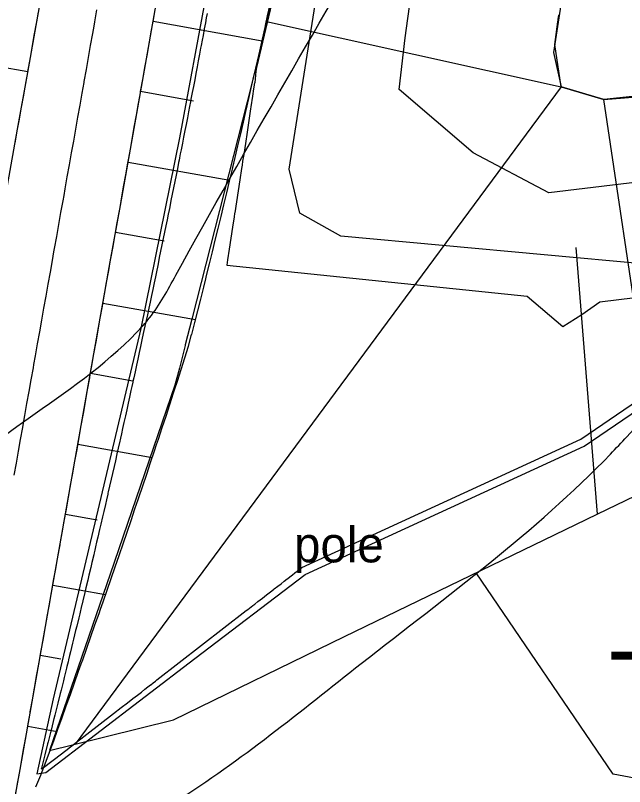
# Model space of a CAD drawing. Extents: x -564043 to -563833, y -1163561 to -1163412.
# Drawn here: x -563931 to -563920.35, y -1163501.37 to -1163487.91 of the extents above; entities that cross this region are included whole.
import ezdxf

# ---------------------------------------------------------------- set-up
doc = ezdxf.new("R2010")
doc.units = 0
for name, color, linetype in [('4', 7, 'Continuous'), ('Default', 7, 'Continuous'), ('Line', 7, 'Continuous'), ('Vrstva 24', 7, 'Continuous'), ('Vrstva 26', 7, 'Continuous'), ('Vrstva 40', 7, 'Continuous')]:
    doc.layers.add(name, color=color, linetype=linetype)

msp = doc.modelspace()

# ---------------------------------------------------------------- linework, layer by layer
msp.add_line((-563930.546, -1163501.066), (-563930.51, -1163501.042))
for points in [[(-563930.469, -1163501.126), (-563927.863, -1163499.14), (-563925.937, -1163497.674), (-563921.059, -1163495.43), (-563912.613, -1163489.681), (-563911.421, -1163482.517), (-563913.266, -1163479.715), (-563914.137, -1163478.749), (-563916.309, -1163476.467), (-563917.281, -1163475.995), (-563923.761, -1163471.506), (-563924, -1163472.797), (-563925.435, -1163477.844), (-563927.008, -1163483.992), (-563927.659, -1163487.507), (-563928.13, -1163490.05), (-563928.806, -1163493.379), (-563930.34, -1163499.841), (-563930.622, -1163501.15)], [(-563915.586, -1163481.384), (-563914.537, -1163483.686), (-563915.595, -1163487.753), (-563917.092, -1163490.681), (-563919.984, -1163492.255), (-563925.31, -1163491.764), (-563926.027, -1163491.364), (-563926.218, -1163490.597), (-563925.375, -1163485.285), (-563924.678, -1163482.734), (-563924.029, -1163478.524), (-563922.899, -1163477.259), (-563919.326, -1163477.602), (-563916.674, -1163478.991)]]:
    msp.add_lwpolyline(points, close=True)
for points in [[(-563925.566, -1163483.68), (-563926.788, -1163488.822), (-563926.795, -1163488.885), (-563926.811, -1163489.025), (-563926.818, -1163489.08), (-563926.823, -1163489.098), (-563926.825, -1163489.11), (-563926.827, -1163489.131), (-563926.837, -1163489.194), (-563926.856, -1163489.32), (-563926.883, -1163489.509), (-563926.89, -1163489.542), (-563926.896, -1163489.586), (-563926.921, -1163489.749), (-563926.952, -1163489.951), (-563926.981, -1163490.148), (-563927.01, -1163490.339), (-563927.028, -1163490.459), (-563927.038, -1163490.526), (-563927.048, -1163490.584), (-563927.078, -1163490.781), (-563927.108, -1163490.976), (-563927.137, -1163491.167), (-563927.166, -1163491.356), (-563927.168, -1163491.368), (-563927.177, -1163491.426), (-563927.205, -1163491.609), (-563927.235, -1163491.802), (-563927.264, -1163491.992), (-563927.292, -1163492.181), (-563927.306, -1163492.273), (-563922.057, -1163492.813), (-563921.435, -1163493.345), (-563921.102, -1163493.131), (-563920.787, -1163492.909), (-563919.265, -1163492.727)], [(-563921.157, -1163485.676), (-563921.598, -1163488.562), (-563921.461, -1163489.159), (-563920.716, -1163489.381), (-563919.058, -1163489.245), (-563919.058, -1163489.245), (-563919.058, -1163489.245), (-563916.75, -1163488.907), (-563916.212, -1163488.994), (-563914.24, -1163489.313), (-563912.713, -1163485.924)], [(-563919.165, -1163490.707), (-563921.676, -1163491.008), (-563923.002, -1163490.31), (-563924.293, -1163489.206), (-563924.187, -1163488.301), (-563923.991, -1163486.868)], [(-563933.061, -1163501.709), (-563932.976, -1163501.232), (-563932.886, -1163500.725), (-563932.71, -1163499.74), (-563932.535, -1163498.756), (-563932.36, -1163497.771), (-563932.185, -1163496.786), (-563932.01, -1163495.802), (-563931.835, -1163494.817), (-563931.659, -1163493.833), (-563931.484, -1163492.848), (-563931.404, -1163492.395), (-563931.309, -1163491.864), (-563931.134, -1163490.879), (-563930.959, -1163489.895), (-563930.784, -1163488.91), (-563930.608, -1163487.926), (-563930.509, -1163487.367)], [(-563931.018, -1163495.937), (-563930.981, -1163495.729), (-563930.944, -1163495.521), (-563930.907, -1163495.313), (-563930.87, -1163495.104), (-563930.85, -1163494.993), (-563930.833, -1163494.896), (-563930.796, -1163494.688), (-563930.759, -1163494.479), (-563930.722, -1163494.271), (-563930.685, -1163494.063), (-563930.675, -1163494.008), (-563930.648, -1163493.854), (-563930.611, -1163493.646), (-563930.573, -1163493.438), (-563930.536, -1163493.23), (-563930.5, -1163493.024), (-563930.499, -1163493.021), (-563930.462, -1163492.813), (-563930.425, -1163492.605), (-563930.388, -1163492.396), (-563930.351, -1163492.188), (-563930.325, -1163492.039), (-563930.314, -1163491.98), (-563930.277, -1163491.771), (-563930.24, -1163491.563), (-563930.203, -1163491.355), (-563930.166, -1163491.147), (-563930.149, -1163491.054), (-563930.129, -1163490.938), (-563930.092, -1163490.73), (-563930.055, -1163490.522), (-563930.018, -1163490.313), (-563929.98, -1163490.105), (-563929.974, -1163490.07), (-563929.943, -1163489.897), (-563929.906, -1163489.688), (-563929.869, -1163489.48), (-563929.832, -1163489.272), (-563929.799, -1163489.085), (-563929.795, -1163489.064), (-563929.758, -1163488.855), (-563929.721, -1163488.647), (-563929.684, -1163488.439), (-563929.647, -1163488.23), (-563929.624, -1163488.101), (-563929.61, -1163488.022), (-563929.573, -1163487.814)], [(-563931.007, -1163501.582), (-563930.917, -1163501.075), (-563930.741, -1163500.09), (-563930.566, -1163499.106), (-563930.391, -1163498.121), (-563930.216, -1163497.137), (-563930.041, -1163496.152), (-563929.866, -1163495.168), (-563929.69, -1163494.183), (-563929.515, -1163493.199), (-563929.435, -1163492.745), (-563929.34, -1163492.214), (-563929.165, -1163491.23), (-563928.99, -1163490.245), (-563928.815, -1163489.261), (-563928.639, -1163488.276), (-563928.54, -1163487.717)], [(-563931.002, -1163490.138), (-563930.965, -1163489.93), (-563930.959, -1163489.895), (-563930.928, -1163489.722), (-563930.891, -1163489.513), (-563930.854, -1163489.305), (-563930.817, -1163489.097), (-563930.784, -1163488.91), (-563930.78, -1163488.888), (-563930.743, -1163488.68), (-563930.706, -1163488.472), (-563930.669, -1163488.264), (-563930.631, -1163488.055), (-563930.608, -1163487.926), (-563930.594, -1163487.847)], [(-563931.002, -1163490.138), (-563930.965, -1163489.93), (-563930.959, -1163489.895), (-563930.928, -1163489.722), (-563930.891, -1163489.513), (-563930.854, -1163489.305), (-563930.817, -1163489.097), (-563930.784, -1163488.91), (-563930.78, -1163488.888), (-563930.743, -1163488.68), (-563930.706, -1163488.472), (-563930.669, -1163488.264), (-563930.631, -1163488.055), (-563930.608, -1163487.926), (-563930.594, -1163487.847)], [(-563930.997, -1163501.528), (-563930.96, -1163501.32), (-563930.923, -1163501.112), (-563930.917, -1163501.075), (-563930.886, -1163500.904), (-563930.849, -1163500.695), (-563930.812, -1163500.487), (-563930.775, -1163500.279), (-563930.741, -1163500.09), (-563930.738, -1163500.07), (-563930.701, -1163499.862), (-563930.664, -1163499.654), (-563930.627, -1163499.445), (-563930.59, -1163499.237), (-563930.566, -1163499.106), (-563930.553, -1163499.029), (-563930.515, -1163498.821), (-563930.478, -1163498.612), (-563930.441, -1163498.404), (-563930.404, -1163498.196), (-563930.391, -1163498.121), (-563930.367, -1163497.987), (-563930.33, -1163497.779), (-563930.293, -1163497.571), (-563930.256, -1163497.362), (-563930.219, -1163497.154), (-563930.216, -1163497.137), (-563930.182, -1163496.946), (-563930.145, -1163496.738), (-563930.108, -1163496.529), (-563930.071, -1163496.321), (-563930.041, -1163496.152), (-563930.034, -1163496.113), (-563929.997, -1163495.904), (-563929.96, -1163495.696), (-563929.922, -1163495.488), (-563929.885, -1163495.279), (-563929.866, -1163495.168), (-563929.848, -1163495.071), (-563929.811, -1163494.863), (-563929.774, -1163494.655), (-563929.737, -1163494.446), (-563929.7, -1163494.238), (-563929.69, -1163494.183), (-563929.663, -1163494.03), (-563929.626, -1163493.821), (-563929.589, -1163493.613), (-563929.552, -1163493.405), (-563929.515, -1163493.199), (-563929.515, -1163493.196), (-563929.478, -1163492.988), (-563929.441, -1163492.78), (-563929.404, -1163492.572), (-563929.367, -1163492.363), (-563929.34, -1163492.214), (-563929.33, -1163492.155), (-563929.292, -1163491.947), (-563929.255, -1163491.738), (-563929.218, -1163491.53), (-563929.181, -1163491.322), (-563929.165, -1163491.23), (-563929.144, -1163491.113), (-563929.107, -1163490.905), (-563929.07, -1163490.697), (-563929.033, -1163490.489), (-563928.996, -1163490.28), (-563928.99, -1163490.245), (-563928.959, -1163490.072), (-563928.922, -1163489.864), (-563928.885, -1163489.655), (-563928.848, -1163489.447), (-563928.815, -1163489.261), (-563928.811, -1163489.239), (-563928.774, -1163489.03), (-563928.737, -1163488.822), (-563928.699, -1163488.614), (-563928.662, -1163488.406), (-563928.639, -1163488.276), (-563928.625, -1163488.197), (-563928.588, -1163487.989), (-563928.551, -1163487.781)], [(-563930.997, -1163501.528), (-563930.96, -1163501.32), (-563930.923, -1163501.112), (-563930.917, -1163501.075), (-563930.886, -1163500.904), (-563930.849, -1163500.695), (-563930.812, -1163500.487), (-563930.775, -1163500.279), (-563930.741, -1163500.09), (-563930.738, -1163500.07), (-563930.701, -1163499.862), (-563930.664, -1163499.654), (-563930.627, -1163499.445), (-563930.59, -1163499.237), (-563930.566, -1163499.106), (-563930.553, -1163499.029), (-563930.515, -1163498.821), (-563930.478, -1163498.612), (-563930.441, -1163498.404), (-563930.404, -1163498.196), (-563930.391, -1163498.121), (-563930.367, -1163497.987), (-563930.33, -1163497.779), (-563930.293, -1163497.571), (-563930.256, -1163497.362), (-563930.219, -1163497.154), (-563930.216, -1163497.137), (-563930.182, -1163496.946), (-563930.145, -1163496.738), (-563930.108, -1163496.529), (-563930.071, -1163496.321), (-563930.041, -1163496.152), (-563930.034, -1163496.113), (-563929.997, -1163495.904), (-563929.96, -1163495.696), (-563929.922, -1163495.488), (-563929.885, -1163495.279), (-563929.866, -1163495.168), (-563929.848, -1163495.071), (-563929.811, -1163494.863), (-563929.774, -1163494.655), (-563929.737, -1163494.446), (-563929.7, -1163494.238), (-563929.69, -1163494.183), (-563929.663, -1163494.03), (-563929.626, -1163493.821), (-563929.589, -1163493.613), (-563929.552, -1163493.405), (-563929.515, -1163493.199), (-563929.515, -1163493.196), (-563929.478, -1163492.988), (-563929.441, -1163492.78), (-563929.404, -1163492.572), (-563929.367, -1163492.363), (-563929.34, -1163492.214), (-563929.33, -1163492.155), (-563929.292, -1163491.947), (-563929.255, -1163491.738), (-563929.218, -1163491.53), (-563929.181, -1163491.322), (-563929.165, -1163491.23), (-563929.144, -1163491.113), (-563929.107, -1163490.905), (-563929.07, -1163490.697), (-563929.033, -1163490.489), (-563928.996, -1163490.28), (-563928.99, -1163490.245), (-563928.959, -1163490.072), (-563928.922, -1163489.864), (-563928.885, -1163489.655), (-563928.848, -1163489.447), (-563928.815, -1163489.261), (-563928.811, -1163489.239), (-563928.774, -1163489.03), (-563928.737, -1163488.822), (-563928.699, -1163488.614), (-563928.662, -1163488.406), (-563928.639, -1163488.276), (-563928.625, -1163488.197), (-563928.588, -1163487.989), (-563928.551, -1163487.781)], [(-563930.64, -1163501.377), (-563930.555, -1163501.177), (-563930.54, -1163501.142), (-563930.476, -1163500.976), (-563930.403, -1163500.775), (-563930.329, -1163500.573), (-563930.256, -1163500.371), (-563930.19, -1163500.188), (-563930.183, -1163500.169), (-563930.111, -1163499.967), (-563930.038, -1163499.765), (-563929.966, -1163499.563), (-563929.894, -1163499.361), (-563929.849, -1163499.234), (-563929.822, -1163499.159), (-563929.751, -1163498.957), (-563929.679, -1163498.754), (-563929.608, -1163498.552), (-563929.537, -1163498.35), (-563929.512, -1163498.278), (-563929.467, -1163498.148), (-563929.396, -1163497.945), (-563929.326, -1163497.743), (-563929.256, -1163497.54), (-563929.186, -1163497.338), (-563929.181, -1163497.321), (-563929.117, -1163497.135), (-563929.048, -1163496.933), (-563928.978, -1163496.73), (-563928.91, -1163496.528), (-563928.854, -1163496.363), (-563928.841, -1163496.325), (-563928.773, -1163496.122), (-563928.704, -1163495.919), (-563928.637, -1163495.717), (-563928.569, -1163495.514), (-563928.533, -1163495.405), (-563928.501, -1163495.311), (-563928.434, -1163495.108), (-563928.367, -1163494.905), (-563928.3, -1163494.702), (-563928.234, -1163494.499), (-563928.216, -1163494.446), (-563928.167, -1163494.296), (-563928.101, -1163494.093), (-563928.036, -1163493.889), (-563927.972, -1163493.686), (-563927.919, -1163493.483), (-563927.918, -1163493.481), (-563927.864, -1163493.275), (-563927.812, -1163493.07), (-563927.76, -1163492.864), (-563927.709, -1163492.658), (-563927.672, -1163492.511), (-563927.658, -1163492.452), (-563927.607, -1163492.247), (-563927.556, -1163492.041), (-563927.506, -1163491.835), (-563927.456, -1163491.629), (-563927.434, -1163491.538), (-563927.406, -1163491.423), (-563927.356, -1163491.217), (-563927.306, -1163491.011), (-563927.257, -1163490.805), (-563927.208, -1163490.598), (-563927.2, -1163490.564), (-563927.159, -1163490.392), (-563927.111, -1163490.186), (-563927.062, -1163489.98), (-563927.014, -1163489.773), (-563926.971, -1163489.589), (-563926.966, -1163489.567), (-563926.918, -1163489.361), (-563926.871, -1163489.154), (-563926.824, -1163488.948), (-563926.776, -1163488.741), (-563926.747, -1163488.613), (-563926.73, -1163488.535), (-563926.683, -1163488.328), (-563926.637, -1163488.121), (-563926.622, -1163488.058), (-563926.592, -1163487.92), (-563926.547, -1163487.722)], [(-563930.64, -1163501.377), (-563930.555, -1163501.177), (-563930.54, -1163501.142), (-563930.476, -1163500.976), (-563930.403, -1163500.775), (-563930.329, -1163500.573), (-563930.256, -1163500.371), (-563930.19, -1163500.188), (-563930.183, -1163500.169), (-563930.111, -1163499.967), (-563930.038, -1163499.765), (-563929.966, -1163499.563), (-563929.894, -1163499.361), (-563929.849, -1163499.234), (-563929.822, -1163499.159), (-563929.751, -1163498.957), (-563929.679, -1163498.754), (-563929.608, -1163498.552), (-563929.537, -1163498.35), (-563929.512, -1163498.278), (-563929.467, -1163498.148), (-563929.396, -1163497.945), (-563929.326, -1163497.743), (-563929.256, -1163497.54), (-563929.186, -1163497.338), (-563929.181, -1163497.321), (-563929.117, -1163497.135), (-563929.048, -1163496.933), (-563928.978, -1163496.73), (-563928.91, -1163496.528), (-563928.854, -1163496.363), (-563928.841, -1163496.325), (-563928.773, -1163496.122), (-563928.704, -1163495.919), (-563928.637, -1163495.717), (-563928.569, -1163495.514), (-563928.533, -1163495.405), (-563928.501, -1163495.311), (-563928.434, -1163495.108), (-563928.367, -1163494.905), (-563928.3, -1163494.702), (-563928.234, -1163494.499), (-563928.216, -1163494.446), (-563928.167, -1163494.296), (-563928.101, -1163494.093), (-563928.036, -1163493.889), (-563927.972, -1163493.686), (-563927.919, -1163493.483), (-563927.918, -1163493.481), (-563927.864, -1163493.275), (-563927.812, -1163493.07), (-563927.76, -1163492.864), (-563927.709, -1163492.658), (-563927.672, -1163492.511), (-563927.658, -1163492.452), (-563927.607, -1163492.247), (-563927.556, -1163492.041), (-563927.506, -1163491.835), (-563927.456, -1163491.629), (-563927.434, -1163491.538), (-563927.406, -1163491.423), (-563927.356, -1163491.217), (-563927.306, -1163491.011), (-563927.257, -1163490.805), (-563927.208, -1163490.598), (-563927.2, -1163490.564), (-563927.159, -1163490.392), (-563927.111, -1163490.186), (-563927.062, -1163489.98), (-563927.014, -1163489.773), (-563926.971, -1163489.589), (-563926.966, -1163489.567), (-563926.918, -1163489.361), (-563926.871, -1163489.154), (-563926.824, -1163488.948), (-563926.776, -1163488.741), (-563926.747, -1163488.613), (-563926.73, -1163488.535), (-563926.683, -1163488.328), (-563926.637, -1163488.121), (-563926.622, -1163488.058), (-563926.592, -1163487.92), (-563926.547, -1163487.722)], [(-563927.649, -1163487.877), (-563927.663, -1163487.953), (-563927.679, -1163488.04), (-563927.698, -1163488.144), (-563927.72, -1163488.262), (-563927.736, -1163488.344), (-563927.753, -1163488.436), (-563927.757, -1163488.458), (-563927.762, -1163488.484), (-563927.782, -1163488.589), (-563927.804, -1163488.706), (-563927.824, -1163488.812), (-563927.846, -1163488.928), (-563927.866, -1163489.034), (-563927.888, -1163489.15), (-563927.909, -1163489.256), (-563927.931, -1163489.372), (-563927.935, -1163489.394), (-563927.94, -1163489.418), (-563927.956, -1163489.502), (-563927.974, -1163489.593), (-563927.994, -1163489.7), (-563928.017, -1163489.815), (-563928.038, -1163489.922), (-563928.06, -1163490.037), (-563928.081, -1163490.144), (-563928.104, -1163490.258), (-563928.117, -1163490.327), (-563928.131, -1163490.4), (-563928.139, -1163490.439), (-563928.147, -1163490.48), (-563928.169, -1163490.588), (-563928.192, -1163490.702), (-563928.213, -1163490.81), (-563928.236, -1163490.923), (-563928.258, -1163491.032), (-563928.28, -1163491.145), (-563928.302, -1163491.253), (-563928.325, -1163491.366), (-563928.327, -1163491.373), (-563928.328, -1163491.38), (-563928.349, -1163491.482), (-563928.37, -1163491.587), (-563928.393, -1163491.696), (-563928.416, -1163491.809), (-563928.438, -1163491.918), (-563928.461, -1163492.03), (-563928.484, -1163492.139), (-563928.507, -1163492.251), (-563928.518, -1163492.305), (-563928.53, -1163492.36), (-563928.541, -1163492.416), (-563928.553, -1163492.473), (-563928.576, -1163492.582), (-563928.6, -1163492.694), (-563928.623, -1163492.803), (-563928.646, -1163492.915), (-563928.669, -1163493.025), (-563928.693, -1163493.136), (-563928.715, -1163493.237), (-563928.736, -1163493.339), (-563928.738, -1163493.348), (-563928.74, -1163493.357), (-563928.764, -1163493.467), (-563928.787, -1163493.578), (-563928.811, -1163493.689), (-563928.835, -1163493.799), (-563928.859, -1163493.911), (-563928.883, -1163494.02), (-563928.908, -1163494.133), (-563928.931, -1163494.241), (-563928.94, -1163494.28), (-563928.948, -1163494.317), (-563928.964, -1163494.392), (-563928.979, -1163494.461), (-563929.005, -1163494.577), (-563929.028, -1163494.682), (-563929.054, -1163494.799), (-563929.077, -1163494.903), (-563929.103, -1163495.021), (-563929.126, -1163495.123), (-563929.147, -1163495.215), (-563929.164, -1163495.294), (-563929.17, -1163495.321), (-563929.175, -1163495.344), (-563929.202, -1163495.465), (-563929.225, -1163495.565), (-563929.252, -1163495.687), (-563929.275, -1163495.785), (-563929.303, -1163495.908), (-563929.325, -1163496.006), (-563929.353, -1163496.13), (-563929.375, -1163496.226), (-563929.381, -1163496.251), (-563929.385, -1163496.271), (-563929.409, -1163496.371), (-563929.426, -1163496.447), (-563929.455, -1163496.574), (-563929.477, -1163496.667), (-563929.507, -1163496.796), (-563929.528, -1163496.887), (-563929.558, -1163497.018), (-563929.579, -1163497.107), (-563929.599, -1163497.191), (-563929.612, -1163497.246), (-563929.623, -1163497.295), (-563929.631, -1163497.328), (-563929.663, -1163497.463), (-563929.683, -1163497.548), (-563929.715, -1163497.685), (-563929.735, -1163497.768), (-563929.768, -1163497.907), (-563929.787, -1163497.988), (-563929.821, -1163498.129), (-563929.84, -1163498.208), (-563929.842, -1163498.216), (-563929.843, -1163498.221), (-563929.875, -1163498.356), (-563929.893, -1163498.428), (-563929.928, -1163498.575), (-563929.946, -1163498.648), (-563929.982, -1163498.798), (-563929.999, -1163498.868), (-563930.036, -1163499.021), (-563930.053, -1163499.088), (-563930.071, -1163499.162), (-563930.079, -1163499.194), (-563930.099, -1163499.275), (-563930.107, -1163499.308), (-563930.146, -1163499.468), (-563930.161, -1163499.527), (-563930.201, -1163499.692), (-563930.215, -1163499.747), (-563930.257, -1163499.916), (-563930.27, -1163499.967), (-563930.309, -1163500.125), (-563930.32, -1163500.167), (-563930.324, -1163500.182), (-563930.325, -1163500.186), (-563930.37, -1163500.367), (-563930.38, -1163500.406), (-563930.427, -1163500.593), (-563930.435, -1163500.626), (-563930.485, -1163500.821), (-563930.491, -1163500.845), (-563930.543, -1163501.05), (-563930.547, -1163501.065)], [(-563919.326, -1163489.233), (-563920.716, -1163489.381), (-563921.461, -1163489.159), (-563921.575, -1163488.419), (-563921.52, -1163488.022), (-563921.519, -1163488.013), (-563921.518, -1163488.005), (-563921.517, -1163487.995), (-563921.516, -1163487.988), (-563921.515, -1163487.978), (-563921.514, -1163487.974), (-563921.514, -1163487.97), (-563921.514, -1163487.97), (-563921.511, -1163487.953), (-563921.508, -1163487.937), (-563921.508, -1163487.935), (-563921.505, -1163487.919), (-563921.504, -1163487.912), (-563921.503, -1163487.901)], [(-563930.51, -1163501.042), (-563930.194, -1163500.802), (-563930.063, -1163500.701), (-563930.031, -1163500.675), (-563930.02, -1163500.666), (-563929.982, -1163500.641), (-563929.282, -1163500.096), (-563929.151, -1163499.995), (-563929.041, -1163499.91), (-563928.948, -1163499.838), (-563928.905, -1163499.805), (-563928.867, -1163499.777), (-563928.798, -1163499.723), (-563928.736, -1163499.676), (-563928.682, -1163499.634), (-563928.637, -1163499.599), (-563928.634, -1163499.597), (-563928.591, -1163499.564), (-563928.553, -1163499.534), (-563928.54, -1163499.524), (-563928.527, -1163499.513), (-563926.965, -1163498.303), (-563926.939, -1163498.283), (-563926.848, -1163498.212), (-563926.816, -1163498.187), (-563926.763, -1163498.146), (-563926.684, -1163498.085), (-563926.61, -1163498.028), (-563926.541, -1163497.974), (-563926.488, -1163497.934), (-563926.476, -1163497.924), (-563926.415, -1163497.876), (-563926.357, -1163497.832), (-563926.303, -1163497.79), (-563926.252, -1163497.75), (-563926.241, -1163497.741), (-563926.203, -1163497.713), (-563926.157, -1163497.677), (-563926.114, -1163497.643), (-563926.073, -1163497.611), (-563926.047, -1163497.591), (-563926.04, -1163497.586), (-563926.033, -1163497.581), (-563925.996, -1163497.552), (-563925.993, -1163497.549), (-563921.117, -1163495.312), (-563912.692, -1163489.565)], [(-563907.591, -1163503.589), (-563920.552, -1163501.157), (-563922.95, -1163497.645)], [(-563930.547, -1163501.065), (-563930.546, -1163501.066)]]:
    msp.add_lwpolyline(points)
at = {"layer": 'Default'}
msp.add_lwpolyline([(-563925.948, -1163485.244), (-563926.867, -1163489.1), (-563927.916, -1163493.212), (-563928.032, -1163493.665), (-563928.034, -1163493.674), (-563928.134, -1163494.067), (-563928.211, -1163494.367), (-563929.345, -1163497.668), (-563930.401, -1163500.745), (-563930.002, -1163500.645), (-563928.239, -1163500.208), (-563925.246, -1163498.757), (-563920.654, -1163496.532), (-563920.013, -1163496.222)], dxfattribs=at)
at = {"layer": 'Line'}
for p, q in [((-563928.592, -1163488.012), (-563926.689, -1163488.356)), ((-563926.609, -1163488.017), (-563921.461, -1163489.159)), ((-563932.909, -1163488.513), (-563930.78, -1163488.892)), ((-563921.461, -1163489.159), (-563929.957, -1163500.634)), ((-563927.889, -1163489.407), (-563928.811, -1163489.242)), ((-563919.728, -1163496.039), (-563920.716, -1163489.381)), ((-563929.03, -1163490.473), (-563927.254, -1163490.789)), ((-563928.399, -1163491.855), (-563929.249, -1163491.704)), ((-563921.206, -1163491.965), (-563920.833, -1163496.619)), ((-563929.468, -1163492.934), (-563927.851, -1163493.222)), ((-563928.949, -1163494.297), (-563929.687, -1163494.165)), ((-563929.906, -1163495.396), (-563928.607, -1163495.627)), ((-563929.568, -1163496.726), (-563930.125, -1163496.626)), ((-563930.344, -1163497.857), (-563929.423, -1163498.021)), ((-563930.203, -1163499.152), (-563930.563, -1163499.088)), ((-563930.782, -1163500.319), (-563930.27, -1163500.41))]:
    msp.add_line(p, q, dxfattribs=at)
at = {"layer": 'Vrstva 24'}
for points in [[(-563939.075, -1163507.623), (-563938.225, -1163507.164), (-563937.324, -1163506.641), (-563936.436, -1163506.097), (-563935.549, -1163505.552), (-563934.649, -1163505.03), (-563930.625, -1163502.906), (-563929.451, -1163502.347), (-563928.196, -1163501.635), (-563924.955, -1163499.225), (-563920.602, -1163495.57), (-563920.316, -1163495.267), (-563915.394, -1163488.268), (-563914.823, -1163487.183), (-563914.579, -1163485.87), (-563914.81, -1163484.102), (-563915.208, -1163482.646), (-563915.847, -1163480.252), (-563916.025, -1163479.9), (-563916.675, -1163479.113), (-563917.077, -1163478.648)], [(-563942.475, -1163518.079), (-563940.112, -1163517.387), (-563935.904, -1163515.974), (-563933.959, -1163515.268), (-563929.245, -1163513.665), (-563925.032, -1163512.173), (-563922.819, -1163511.166), (-563919.003, -1163509.075), (-563915.156, -1163506.928), (-563914.035, -1163506.214), (-563913.139, -1163505.478), (-563911.421, -1163503.905), (-563910.565, -1163503.115), (-563909.689, -1163502.349), (-563908.668, -1163501.532), (-563907.622, -1163500.746), (-563906.572, -1163499.965), (-563905.922, -1163499.466)]]:
    msp.add_spline(points, degree=3, dxfattribs=at)
at = {"layer": 'Vrstva 26'}
for points in [[(-563938.486, -1163500.528), (-563938.463, -1163500.513), (-563937.665, -1163500.022), (-563936.97, -1163499.566), (-563930.777, -1163494.949), (-563928.884, -1163493.45), (-563928.656, -1163493.192), (-563928.195, -1163492.447), (-563924.372, -1163485.735), (-563923.788, -1163484.5), (-563923.604, -1163483.639), (-563923.611, -1163481.604), (-563923.712, -1163481.017), (-563924.518, -1163478.475), (-563924.689, -1163477.919), (-563924.751, -1163477.798), (-563925.518, -1163476.583), (-563926.306, -1163475.384), (-563927.092, -1163474.184), (-563927.851, -1163472.968), (-563928.532, -1163471.813), (-563929.192, -1163470.645), (-563929.849, -1163469.476), (-563930.525, -1163468.317), (-563930.688, -1163468.07), (-563931.156, -1163467.471), (-563931.276, -1163467.321)], [(-563940.525, -1163513.198), (-563938.9, -1163512.504), (-563932.611, -1163509.84), (-563931.885, -1163509.567), (-563930.901, -1163509.188), (-563926.659, -1163507.216), (-563923.334, -1163505.549), (-563921.652, -1163504.643), (-563920.105, -1163503.651), (-563917.012, -1163501.201), (-563913.048, -1163497.944), (-563912.649, -1163497.606), (-563912.385, -1163497.353), (-563911.289, -1163496.159), (-563908.991, -1163493.383), (-563906.775, -1163490.536), (-563906.699, -1163490.433)]]:
    msp.add_spline(points, degree=3, dxfattribs=at)

# ---------------------------------------------------------------- texts
at = {"layer": '4'}
msp.add_text('TŮŇ T2', height=1.25, rotation=360, dxfattribs=at).set_placement((-563920.624, -1163500.27))
at = {"layer": 'Vrstva 40'}
msp.add_text('pole', height=0.62, dxfattribs=at).set_placement((-563926.13, -1163497.46))

doc.saveas('drawing.dxf')
